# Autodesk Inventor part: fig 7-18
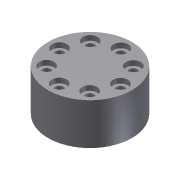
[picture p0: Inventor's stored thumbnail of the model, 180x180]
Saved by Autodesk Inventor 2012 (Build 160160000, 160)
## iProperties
Created: 2004-05
Part Number: fig 7-18
Document SubType Name: Modeling
Designer: CADCIM Technologies
Manufacturer: Standard
Standards Organization: Custom
Density: 1 g/cm^3
Material: Default
Author: CADCIM Technologies
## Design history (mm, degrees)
sketch "Sketch1"
  geometry: C1 r 17.175 at (0, 0)
  constraints: 1 centre point
extrude "Extrusion1" new body sketch "Sketch1" distance "d0" = 17; taper "d1" = 0 deg
sketch "Sketch2"
  geometry: 1 further point
hole "Hole1" sketch "Sketch2" at (12.571, -0.074) diameter "d2" = 3.5; stored, may be unused: countersink angle "d6" = 90 deg, drill point angle "d8" = 118 deg; dims "d3" = 6, "d4" = 6, "d5" = 2, "d7" = 8
pattern_circular "Circular Pattern1" dims angle "d11" = 360 deg
body "Solid1"
